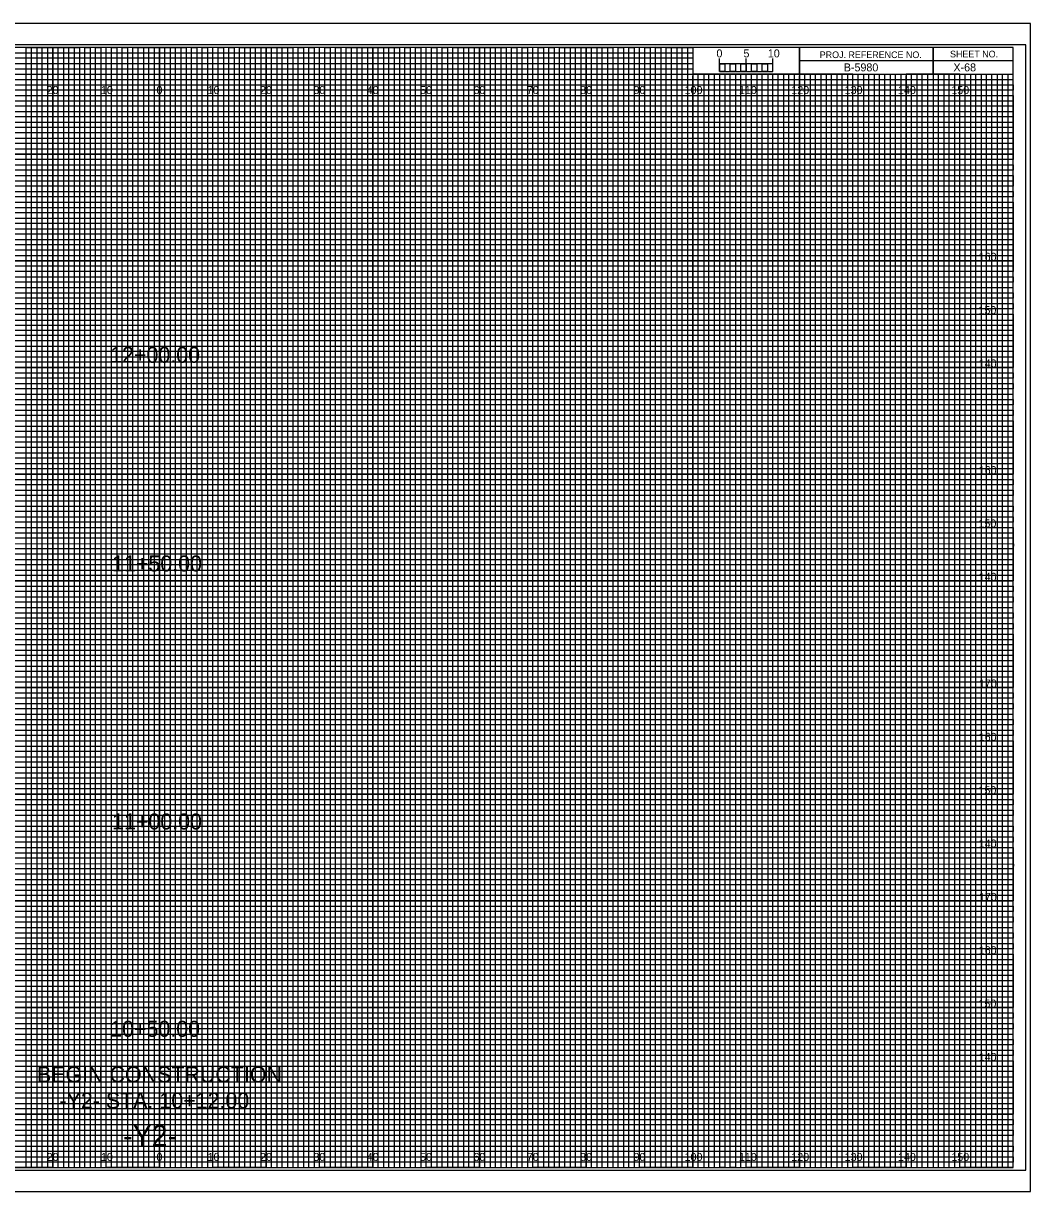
# Model space of a CAD drawing. Extents: x -13 to 323, y -5 to 434.
# Drawn here: x 134.5 to 323.3, y -4.5 to 214.5 of the extents above; entities that cross this region are included whole.
import ezdxf

# ---------------------------------------------------------------- set-up
doc = ezdxf.new("R2010")
doc.units = 0
for name, color, linetype in [('Exist CMT Pavement', 7, 'Continuous'), ('Exist Cross Section Cell', 7, 'Continuous'), ('Exist XS Center Line Elevation Label', 7, 'Continuous'), ('Exist XS Ground Line', 7, 'Continuous'), ('Prop CMT Pvmt Course 1', 7, 'Continuous'), ('Prop CMT Pvmt Course 1 Wedge', 7, 'Continuous'), ('Prop CMT Pvmt Course 2', 7, 'Continuous'), ('Prop CMT Pvmt Course 2 Wedge', 7, 'Continuous'), ('Prop CMT Pvmt Course 3', 7, 'Continuous'), ('Prop CMT Pvmt Course 3 Wedge', 7, 'Continuous'), ('Prop CMT Pvmt Surface', 7, 'Continuous'), ('Prop CMT Pvmt Surface Shoulder', 7, 'Continuous'), ('Prop CMT Shld Paved Course 1', 7, 'Continuous'), ('Prop CMT Shld Paved Course 2', 7, 'Continuous'), ('Prop CMT Shld Paved Course 3', 7, 'Continuous'), ('Prop CMT Slope Grass', 7, 'Continuous'), ('Prop CMT Subgrade Earthwork', 7, 'Continuous')]:
    doc.layers.add(name, color=color, linetype=linetype)

msp = doc.modelspace()

# ---------------------------------------------------------------- linework, layer by layer
at = {"layer": 'Exist XS Center Line Elevation Label'}
for points in [[(125, 0), (135, 0), (135, 210), (145, 210), (145, 0), (155, 0), (155, 210), (165, 210), (165, 0), (175, 0), (175, 210), (185, 210), (185, 0), (195, 0), (195, 210), (205, 210), (205, 0), (215, 0), (215, 210), (225, 210), (225, 0), (235, 0), (235, 210), (245, 210), (245, 0), (255, 0), (255, 210), (259.93, 210), (260, 210), (260, 205), (264.99, 205), (264.99, 0), (275, 0), (275, 205), (285, 205), (285, 0), (295, 0), (295, 205), (305, 205), (305, 0), (315, 0), (315, 205)], [(0, 205), (275, 205)], [(0, 185), (320, 185), (320, 195), (0, 195)], [(0, 165), (320, 165), (320, 175), (0, 175)], [(0, 145), (320, 145), (320, 155), (0, 155)], [(0, 125), (320, 125), (320, 135), (0, 135)], [(0, 105), (320, 105), (320, 115), (0, 115)], [(0, 85), (320, 85), (320, 95), (0, 95)], [(0, 65), (320, 65), (320, 75), (0, 75)], [(0, 45), (320, 45), (320, 55), (0, 55)], [(0, 25), (320, 25), (320, 35), (0, 35)], [(0, 5), (320, 5), (320, 15), (0, 15)]]:
    msp.add_lwpolyline(points, dxfattribs=at)
at = {"layer": 'Exist XS Ground Line'}
for p, q in [((150, 210), (140, 210)), ((140, 210), (140, 0)), ((150, 0), (150, 210)), ((170, 210), (160, 210)), ((160, 210), (160, 0)), ((170, 0), (170, 210)), ((190, 210), (180, 210)), ((180, 210), (180, 0)), ((190, 0), (190, 210)), ((210, 210), (200, 210)), ((200, 210), (200, 0)), ((210, 0), (210, 210)), ((230, 210), (220, 210)), ((220, 210), (220, 0)), ((230, 0), (230, 210)), ((250, 210), (240, 210)), ((240, 210), (240, 0)), ((250, 0), (250, 210)), ((260, 210), (260, 0)), ((270, 0), (270, 205)), ((290, 205), (280, 205)), ((280, 205), (280, 0)), ((290, 0), (290, 205)), ((310, 205), (300, 205)), ((300, 205), (300, 0)), ((310, 0), (310, 205)), ((140, 0), (130, 0)), ((160, 0), (150, 0)), ((180, 0), (170, 0)), ((200, 0), (190, 0)), ((220, 0), (210, 0)), ((240, 0), (230, 0)), ((260, 0), (250, 0)), ((280, 0), (270, 0)), ((300, 0), (290, 0)), ((320, 0), (310, 0)), ((320, 0), (320, 0))]:
    msp.add_line(p, q, dxfattribs=at)
for points in [[(0, 200), (320, 200), (320, 190), (0, 190)], [(0, 180), (320, 180), (320, 170), (0, 170)], [(0, 160), (320, 160), (320, 150), (0, 150)], [(0, 140), (320, 140), (320, 130), (0, 130)], [(0, 120), (320, 120), (320, 110), (0, 110)], [(0, 100), (320, 100), (320, 90), (0, 90)], [(0, 80), (320, 80), (320, 70), (0, 70)], [(0, 60), (320, 60), (320, 50), (0, 50)], [(0, 40), (320, 40), (320, 30), (0, 30)], [(0, 20), (320, 20), (320, 10), (0, 10)]]:
    msp.add_lwpolyline(points, dxfattribs=at)
at = {"layer": 'Prop CMT Pvmt Course 2'}
for p, q in [((265, 205.49), (265, 207.9)), ((265, 206.9), (265, 207.9)), ((270, 205.49), (270, 207.9)), ((275, 205.49), (275, 207.9)), ((275, 206.9), (275, 207.9))]:
    msp.add_line(p, q, dxfattribs=at)
for points in [[(275, 206.9), (265, 206.9), (265, 205.49), (275, 205.49)], [(265, 206.9), (266, 206.9), (266, 205.49), (265, 205.49)], [(267, 206.9), (268, 206.9), (268, 205.49), (267, 205.49)], [(269, 206.9), (270, 206.9), (270, 205.49), (269, 205.49)], [(271, 206.9), (272, 206.9), (272, 205.49), (271, 205.49)], [(273, 206.9), (274, 206.9), (274, 205.49), (273, 205.49)]]:
    msp.add_lwpolyline(points, close=True, dxfattribs=at)
at = {"layer": 'Prop CMT Pvmt Course 3'}
msp.add_lwpolyline([(-13.4, -4.5), (323.3, -4.5), (323.3, 214.5), (-13.4, 214.5)], close=True, dxfattribs=at)
at = {"layer": 'Prop CMT Pvmt Surface'}
for p, q in [((140, 0), (140, 210)), ((150, 0), (150, 210)), ((160, 0), (160, 210)), ((170, 0), (170, 210)), ((180, 0), (180, 210)), ((190, 0), (190, 210)), ((200, 0), (200, 210)), ((210, 0), (210, 210)), ((220, 0), (220, 210)), ((230, 0), (230, 210)), ((240, 0), (240, 210)), ((250, 0), (250, 210)), ((260, 0), (260, 204.69)), ((270, 0), (270, 204.69)), ((280, 0), (280, 204.69)), ((290, 0), (290, 204.69)), ((300, 0), (300, 204.69)), ((310, 0), (310, 204.69)), ((0, 200), (320, 200)), ((0, 190), (320, 190)), ((0, 180), (320, 180)), ((0, 170), (320, 170)), ((0, 160), (320, 160)), ((0, 150), (320, 150)), ((0, 140), (320, 140)), ((0, 130), (320, 130)), ((0, 120), (320, 120)), ((0, 110), (320, 110)), ((0, 100), (320, 100)), ((0, 90), (320, 90)), ((0, 80), (320, 80)), ((0, 70), (320, 70)), ((0, 60), (320, 60)), ((0, 50), (320, 50)), ((0, 40), (320, 40)), ((0, 30), (320, 30)), ((0, 20), (320, 20)), ((0, 10), (320, 10))]:
    msp.add_line(p, q, dxfattribs=at)
at = {"layer": 'Prop CMT Pvmt Surface Shoulder'}
for p, q in [((323.3, 214.5), (-13.4, 214.5)), ((-13.4, -4.5), (323.3, -4.5))]:
    msp.add_line(p, q, dxfattribs=at)
at = {"layer": 'Prop CMT Shld Paved Course 1'}
for p, q in [((0, 209), (260, 209)), ((260, 209), (260, 207.98)), ((260, 207.98), (0, 207.98)), ((0, 207), (260, 207)), ((260, 205.89), (0, 205.89)), ((260, 207), (260, 205.89)), ((0, 204), (320, 204))]:
    msp.add_line(p, q, dxfattribs=at)
for points in [[(0, 203), (270, 203), (320, 203), (320, 202), (0, 202)], [(0, 201), (320, 201), (320, 199), (0, 199)], [(0, 198), (320, 198), (320, 197), (0, 196.98)], [(0, 196), (320, 196), (320, 194), (0, 194)], [(0, 193), (320, 193), (320, 192), (0, 192)], [(0, 191), (320, 191), (320, 189), (0, 189)], [(0, 188), (320, 188), (320, 187), (0, 187)], [(0, 186), (320, 186), (320, 184), (0, 184)], [(0, 183), (320, 183), (320, 182), (0, 182)], [(0, 181), (320, 181), (320, 179), (0, 179)], [(0, 178), (320, 178), (320, 177), (0, 177)], [(0, 176), (320, 176), (320, 173.95), (320, 173), (320, 172), (0, 172)], [(0, 174), (320, 174), (320, 173), (0, 173)], [(0, 171), (320, 171), (320, 169), (0, 169.03)], [(0, 169.03), (320, 169), (320, 168), (0, 168)], [(0, 167), (320, 167), (320, 166), (0, 166)], [(0, 164), (320, 164), (320, 163), (0, 163)], [(0, 162), (320, 162), (320, 161), (0, 161)], [(-0.07, 158.89), (320, 158.89), (320, 157.88), (-0.07, 157.88)], [(0, 157), (320, 157), (320, 156), (0, 156)], [(0, 154), (320, 154), (320, 153), (0, 153)], [(0, 152), (320, 152), (320, 151), (0, 151)], [(0, 149), (320, 149), (320, 148), (0, 148)], [(0, 147), (320, 147), (320, 146), (0, 146)], [(0, 144), (320, 144), (320, 143), (0, 143)], [(0, 142), (320, 142), (320, 141), (0, 141)], [(0, 139), (320, 139), (319.99, 137.98), (0, 138)], [(0, 137), (320, 137), (320, 136), (0, 136)], [(0, 134), (320, 134), (320, 133), (0, 133)], [(0, 132), (320, 132), (320, 131), (0, 131)], [(0, 129), (320, 129), (320, 128), (0, 128)], [(0, 127), (320, 127), (320, 126), (0, 126)], [(0, 124), (320, 124), (320, 123), (0, 123)], [(0, 122), (320, 122), (320, 121), (0, 121)], [(0, 119), (320, 119), (320, 118), (0, 118)], [(0, 116.99), (320.07, 116.91), (320, 116), (0, 116)], [(0, 114), (320, 114), (320, 113), (0, 113)], [(0, 112), (320, 112), (320, 111), (0, 111)], [(0, 109), (320, 109), (320, 108), (0, 108)], [(0, 107), (320, 107), (320, 106), (0, 106)], [(0, 104), (320, 104), (320, 103), (0, 103)], [(0, 102), (320, 102), (320, 101), (0, 101)], [(0, 99), (320, 99), (320, 98), (0, 98)], [(0, 97), (320, 97), (320, 96), (0, 96)], [(0, 94), (320, 94), (320, 93), (0, 93)], [(0, 92), (320, 92), (320, 91), (0, 91)], [(0, 89), (320, 89), (320, 88), (0, 88)], [(0, 87), (320, 87), (320, 86), (0, 86)], [(0, 84), (320, 84), (320, 83), (0, 83)], [(0, 82), (320, 82), (320, 81), (0, 81)], [(0, 79), (320, 79), (319.99, 77.98), (0, 78)], [(0, 77), (320, 77), (320, 76), (0, 76)], [(0, 74), (320, 74), (320, 73), (0, 73)], [(0, 72), (320, 72), (320, 71), (0, 71)], [(0, 69), (320, 69), (320, 68), (0, 68)], [(0, 67), (320, 67), (320, 66), (0, 66)], [(0, 64), (320, 64), (320, 63), (0, 63)], [(0, 62), (320, 62), (320, 61), (0, 61)], [(0, 59), (320, 59), (320, 58), (0, 58)], [(0, 56.99), (320.07, 56.91), (320, 56), (0, 56)], [(0, 54), (320, 54), (320, 53), (0, 53)], [(0, 52), (320, 52), (320, 51), (0, 51)], [(0, 49), (320, 49), (320, 48), (0, 48)], [(0, 47), (320, 47), (320, 46), (0, 46)], [(0, 44), (320, 44), (320, 43), (0, 43)], [(0, 42), (320, 42), (320, 41), (0, 41)], [(0, 39), (320, 39), (320, 38), (0, 38)], [(0, 37), (320, 37), (320, 36), (0, 36)], [(0, 34), (320, 34), (320, 33), (0, 33)], [(0, 32), (320, 32), (320, 31), (0, 31)], [(0, 29), (320, 29), (320, 28), (0, 28)], [(0, 27), (320, 27), (320, 26), (0, 26)], [(0, 24), (320, 24), (320, 23), (0, 23)], [(0, 22), (320, 22), (320, 21), (0, 21)], [(0, 19), (320, 19), (320, 18), (0, 18)], [(0, 17), (320, 17), (320, 16), (0, 16)], [(0, 14), (320, 14), (320, 13), (0, 13)], [(0, 12), (320, 12), (320, 11), (0, 11)], [(0, 9), (320, 9), (320, 8), (0, 8)], [(0, 7), (320, 7), (320, 6), (0, 6)], [(0, 4), (320, 4), (320, 3), (0, 3)], [(0, 2), (320, 2), (320, 1), (0, 1)]]:
    msp.add_lwpolyline(points, dxfattribs=at)
at = {"layer": 'Prop CMT Shld Paved Course 2'}
for p, q in [((305, 210), (305, 205)), ((305, 205), (305, 210)), ((280, 207.5), (280, 205)), ((320, 207.49), (280, 207.49)), ((280, 205), (320, 205))]:
    msp.add_line(p, q, dxfattribs=at)
for points in [[(320, 210), (0, 210), (0, 0), (320, 0)], [(280, 210), (260, 210), (260, 205.03), (280, 205.03)], [(320, 210), (280, 210), (280, 205), (320, 205)]]:
    msp.add_lwpolyline(points, close=True, dxfattribs=at)
at = {"layer": 'Prop CMT Shld Paved Course 3'}
for p, q in [((267, 205), (266.01, 205)), ((266.01, 205), (266.01, 0)), ((267, 0), (267, 205)), ((269, 205), (268, 205)), ((268, 205), (268, 0)), ((269, 0), (269, 205)), ((266.01, 0), (265, 0)), ((268, 0), (267, 0))]:
    msp.add_line(p, q, dxfattribs=at)
for points in [[(135, 0), (136, 0), (136, 210), (137, 210), (137, 0)], [(137, 0), (138, 0), (138, 210), (139, 210), (139, 0)], [(140, 0), (141, 0), (141, 210), (142, 210), (142, 0)], [(142, 0), (143, 0), (143, 210), (144, 210), (144, 0)], [(145, 0), (146, 0), (146, 210), (147, 210), (147, 0)], [(147, 0), (148, 0), (148, 210), (149, 210), (149, 0)], [(150, 0), (151, 0), (151, 210), (152, 210), (152, 0)], [(152, 0), (153, 0), (153, 210), (154, 210), (154, 0)], [(155, 0), (156, 0), (156, 210), (157, 210), (157, 0)], [(157, 0), (158, 0), (158, 210), (159, 210), (159, 0)], [(160, 0), (161, 0), (161, 210), (162, 210), (162, 0)], [(162, 0), (163, 0), (163, 210), (164, 210), (164, 0)], [(165, 0), (166, 0), (166, 210), (167, 210), (167, 0)], [(167, 0), (168, 0), (168, 210), (169, 210), (169, 0)], [(170, 0), (171, 0), (171, 210), (172, 210), (172, 0)], [(172, 0), (173, 0), (173, 210), (174, 210), (174, 0)], [(175, 0), (176, 0), (176, 210), (177, 210), (177, 0)], [(177, 0), (178, 0), (178, 210), (179, 210), (179, 0)], [(180, 0), (181, 0), (181, 210), (182, 210), (182, 0)], [(182, 0), (183, 0), (183, 210), (184, 210), (184, 0)], [(185, 0), (186, 0), (186, 210), (187, 210), (187, 0)], [(187, 0), (188, 0), (188, 210), (189, 210), (189, 0)], [(190, 0), (191, 0), (191, 210), (192, 210), (192, 0)], [(192, 0), (193, 0), (193, 210), (194, 210), (194, 0)], [(195, 0), (196, 0), (196, 210), (197, 210), (197, 0)], [(197, 0), (198, 0), (198, 210), (199, 210), (199, 0)], [(200, 0), (201, 0), (201, 210), (202, 210), (202, 0)], [(202, 0), (203, 0), (203, 210), (204, 210), (204, 0)], [(205, 0), (206, 0), (206, 210), (207, 210), (207, 0)], [(207, 0), (208, 0), (208, 210), (209, 210), (209, 0)], [(210, 0), (211, 0), (211, 210), (212, 210), (212, 0)], [(212, 0), (213, 0), (213, 210), (214, 210), (214, 0)], [(215, 0), (216, 0), (216, 210), (217, 210), (217, 0)], [(217, 0), (218, 0), (218, 210), (219, 210), (219, 0)], [(220, 0), (221, 0), (221, 210), (222, 210), (222, 0)], [(222, 0), (223, 0), (223, 210), (224, 210), (224, 0)], [(225, 0), (226, 0), (226, 210), (227, 210), (227, 0)], [(227, 0), (228, 0), (228, 210), (229, 210), (229, 0)], [(230, 0), (231, 0), (231, 210), (232, 210), (232, 0)], [(232, 0), (233, 0), (233, 210), (234, 210), (234, 0)], [(235, 0), (236, 0), (236, 210), (237, 210), (237, 0)], [(237, 0), (238, 0), (238, 210), (239, 210), (239, 0)], [(240, 0), (241, 0), (241, 210), (242, 210), (242, 0)], [(242, 0), (243, 0), (243, 210), (244, 210), (244, 0)], [(245, 0), (246, 0), (246, 210), (247, 210), (247, 0)], [(247, 0), (248, 0), (248, 210), (249, 210), (249, 0)], [(250, 0), (251, 0), (251, 210), (252, 210), (252, 0)], [(252, 0), (253, 0), (253, 210), (254, 210), (254, 0)], [(255, 0), (256, 0), (256, 210), (257, 210), (257, 0)], [(257, 0), (258, 0), (258, 210), (259, 210), (259, 0)], [(260, 0), (261, 0), (261, 205), (262.02, 205), (262.02, 0)], [(262, 0), (263, 0), (263, 205), (263.99, 205), (263.99, 0)], [(270, 0), (270.98, 0), (270.98, 205), (272, 205), (272, 0)], [(272, 0), (273, 0), (273, 205), (274.05, 205), (274.05, 0)], [(275, 0), (276, 0), (276, 205), (277, 205), (277, 0)], [(277, 0), (278, 0), (278, 205), (279, 205), (279, 0)], [(280, 0), (281, 0), (281, 205), (282, 205), (282, 0)], [(282, 0), (283, 0), (283, 205), (284, 205), (284, 0)], [(285, 0), (286, 0), (286, 205), (287, 205), (287, 0)], [(287, 0), (288, 0), (288, 205), (289, 205), (289, 0)], [(290, 0), (291, 0), (291, 205), (292, 205), (292, 0)], [(292, 0), (293, 0), (293, 205), (294, 205), (294, 0)], [(295, 0), (296, 0), (296, 205), (297, 205), (297, 0)], [(297, 0), (298, 0), (298, 205), (299, 205), (299, 0)], [(300, 0), (301, 0), (301, 205), (302, 205), (302, 0)], [(302, 0), (303, 0), (303, 205), (304, 205), (304, 0)], [(305, 0), (306, 0), (306, 205), (307, 205), (307, 0)], [(307, 0), (308, 0), (308, 205), (309, 205), (309, 0)], [(310, 0), (311, 0), (311, 205), (312, 205), (312, 0)], [(312, 0), (313, 0), (313, 205), (314, 205), (314, 0)], [(315, 0), (316, 0), (316, 205), (317, 205), (317, 0)], [(317, 0), (318, 0), (318, 205), (319, 205), (319, 0)]]:
    msp.add_lwpolyline(points, dxfattribs=at)
at = {"layer": 'Prop CMT Subgrade Earthwork'}
msp.add_lwpolyline([(-10.8, -0.5), (322.4, -0.5), (322.4, 210.5), (-10.8, 210.5)], close=True, dxfattribs=at)

# ---------------------------------------------------------------- texts
at = {"layer": 'Exist CMT Pavement'}
for s, p in [('5', (269.47, 208.12)), ('10', (274.04, 208.12))]:
    msp.add_text(s, height=1.5, dxfattribs=at).set_placement(p)
at = {"layer": 'Exist Cross Section Cell'}
for s, p in [('20', (138.86, 201.25)), ('10', (149.04, 201.25)), ('0', (159.45, 201.25)), ('0', (159.45, 201.25)), ('10', (169.04, 201.25)), ('20', (178.86, 201.25)), ('30', (188.86, 201.25)), ('40', (198.86, 201.25)), ('50', (208.86, 201.25)), ('60', (218.86, 201.25)), ('70', (228.86, 201.25)), ('80', (238.86, 201.25)), ('90', (248.86, 201.25)), ('100', (258.44, 201.25)), ('110', (268.62, 201.25)), ('120', (278.44, 201.25)), ('130', (288.44, 201.25)), ('140', (298.44, 201.25)), ('150', (308.44, 201.25)), ('20', (138.86, 1.25)), ('10', (149.04, 1.25)), ('0', (159.45, 1.25)), ('0', (159.45, 1.25)), ('10', (169.04, 1.25)), ('20', (178.86, 1.25)), ('30', (188.86, 1.25)), ('40', (198.86, 1.25)), ('50', (208.86, 1.25)), ('60', (218.86, 1.25)), ('70', (228.86, 1.25)), ('80', (238.86, 1.25)), ('90', (248.86, 1.25)), ('100', (258.44, 1.25)), ('110', (268.62, 1.25)), ('120', (278.44, 1.25)), ('130', (288.44, 1.25)), ('140', (298.44, 1.25)), ('150', (308.44, 1.25))]:
    msp.add_text(s, height=1.5, dxfattribs=at).set_placement(p)
at = {"layer": 'Prop CMT Pvmt Course 1'}
for s, p in [('160', (313.57, 170)), ('150', (313.52, 160)), ('140', (313.57, 150)), ('160', (313.57, 130)), ('150', (313.52, 120)), ('140', (313.57, 110)), ('170', (313.61, 90)), ('160', (313.57, 80)), ('150', (313.52, 70)), ('140', (313.57, 60)), ('170', (313.61, 50)), ('160', (313.57, 40)), ('150', (313.52, 30)), ('140', (313.57, 20))]:
    msp.add_text(s, height=1.5, dxfattribs=at).set_placement(p)
at = {"layer": 'Prop CMT Pvmt Course 1 Wedge'}
msp.add_text('X-68', height=1.5, dxfattribs=at).set_placement((308.83, 205.5))
at = {"layer": 'Prop CMT Pvmt Course 2'}
msp.add_text('0', height=1.5, dxfattribs=at).set_placement((264.41, 208.12))
at = {"layer": 'Prop CMT Pvmt Course 2 Wedge'}
msp.add_text('B-5980', height=1.5, dxfattribs=at).set_placement((288.28, 205.5))
at = {"layer": 'Prop CMT Pvmt Course 3 Wedge'}
msp.add_text('-Y2-', height=4, dxfattribs=at).set_placement((153.21, 4))
at = {"layer": 'Prop CMT Shld Paved Course 2'}
for s, p in [('PROJ. REFERENCE NO.', (283.77, 207.99)), ('SHEET NO.', (308.19, 208.12))]:
    msp.add_text(s, height=1.25, dxfattribs=at).set_placement(p)
at = {"layer": 'Prop CMT Slope Grass'}
for s, p in [('12+00.00', (150.77, 150.87)), ('11+50.00', (151.13, 111.76)), ('11+00.00', (151.13, 63.39)), ('10+50.00', (150.77, 24.52)), ('BEGIN CONSTRUCTION', (137.05, 15.97)), ('-Y2- STA. 10+12.00', (141.27, 11.1))]:
    msp.add_text(s, height=3, dxfattribs=at).set_placement(p)

doc.saveas('drawing.dxf')
